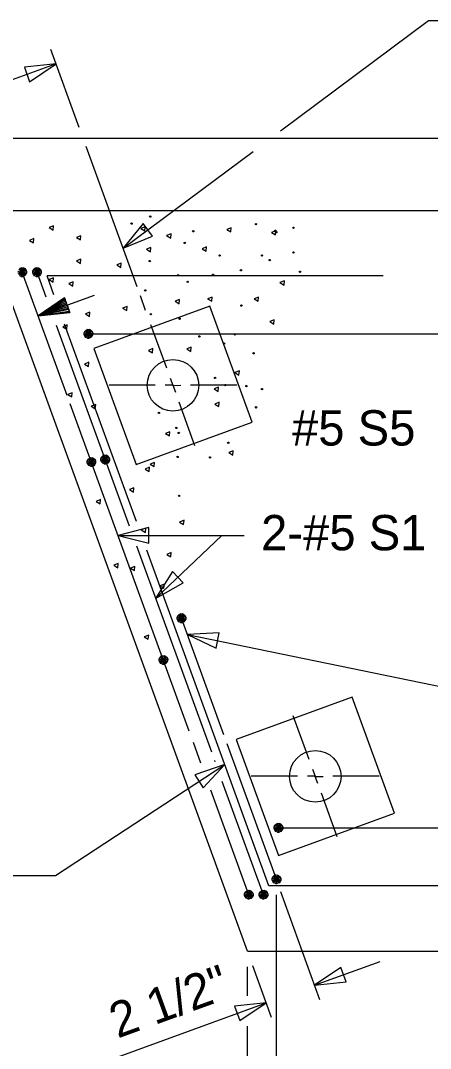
# Model space of a CAD drawing. Extents: x 0 to 177, y -1 to 130.
# Drawn here: x 127.362 to 129.022, y 89.921 to 94.083 of the extents above; entities that cross this region are included whole.
import ezdxf

# ---------------------------------------------------------------- set-up
doc = ezdxf.new("R2010")
doc.units = 0
for name, color, linetype in [('Arrowhead Terminators CELL', 7, 'Continuous'), ('Dimension Lines', 7, 'Continuous'), ('Rebar Lines', 7, 'Continuous'), ('Sup Concrete Girder Lines', 7, 'Continuous'), ('Sup Cored Slab Unit', 7, 'Continuous'), ('Text', 7, 'Continuous')]:
    doc.layers.add(name, color=color, linetype=linetype)

msp = doc.modelspace()

# ---------------------------------------------------------------- linework, layer by layer
at = {"layer": 'Arrowhead Terminators CELL'}
for points in [[(127.5058, 93.9076), (127.3776, 93.8942), (127.399, 93.8354)], [(127.7774, 93.1611), (127.8963, 93.2108), (127.859, 93.2609)], [(127.757, 91.9988), (127.882, 91.9675), (127.8819, 92.03)], [(127.9083, 91.7434), (128.0204, 91.8069), (127.9773, 91.8522)], [(128.0376, 91.5979), (128.1537, 91.5421), (128.1663, 91.6034)], [(128.1893, 91.0712), (128.0676, 91.0288), (128.1019, 90.9765)], [(128.5529, 90.1772), (128.6811, 90.1906), (128.6597, 90.2493)], [(128.3572, 90.1059), (128.2291, 90.0926), (128.2504, 90.0338)]]:
    msp.add_lwpolyline(points, close=True, dxfattribs=at)
at = {"layer": 'Dimension Lines'}
for p, q in [((127.5996, 93.6496), (127.4843, 93.9663)), ((127.5058, 93.9076), (127.0359, 93.7366)), ((130.9813, 93.6051), (127.1894, 93.6051)), ((127.834, 93.0056), (127.6275, 93.573)), ((127.6608, 92.9704), (127.4335, 92.8876)), ((127.8688, 92.9098), (127.8474, 92.9686)), ((127.9545, 92.675), (127.8903, 92.8511)), ((127.9079, 92.6064), (127.7204, 92.6063)), ((128.2385, 92.6063), (128.051, 92.6063)), ((128.0685, 92.3615), (128.0044, 92.5377)), ((127.757, 91.9988), (128.1767, 91.9988)), ((128.5305, 91.0918), (128.4664, 91.268)), ((128.4839, 91.0232), (128.2964, 91.0232)), ((128.8146, 91.0232), (128.627, 91.0232)), ((128.6446, 90.7784), (128.5804, 90.9545)), ((128.3985, 89.6325), (128.3985, 90.5438)), ((128.5743, 90.1184), (128.4156, 90.5548)), ((128.5529, 90.1772), (128.8183, 90.2738)), ((128.2813, 90.1345), (128.2813, 90.2521)), ((128.3786, 90.0472), (128.3027, 90.2559)), ((127.7272, 89.8766), (128.3572, 90.1059)), ((128.2813, 88.9658), (128.2813, 90.0109))]:
    msp.add_line(p, q, dxfattribs=at)
for points in [[(128.4152, 93.6366), (129.0144, 94.0831), (129.5734, 94.0831)], [(127.7774, 93.1611), (128.3039, 93.5535)], [(127.5509, 92.9304), (127.5531, 92.9246), (127.4335, 92.8876), (127.5553, 92.9187), (127.5574, 92.9128), (127.4335, 92.8876), (127.5595, 92.9069), (127.5616, 92.9011), (127.4335, 92.8876), (127.5402, 92.9598), (127.5424, 92.9538), (127.4335, 92.8876), (127.5445, 92.948), (127.5467, 92.9421), (127.4335, 92.8876), (127.5489, 92.9363), (127.5616, 92.9011), (127.5402, 92.9598), (127.4335, 92.8876), (127.5616, 92.9011)], [(127.9686, 92.6357), (127.9794, 92.6063), (127.9479, 92.6062)], [(127.9904, 92.5766), (127.9797, 92.6061), (128.0111, 92.6062)], [(127.9083, 91.7434), (128.1767, 91.9988), (128.2676, 91.9988)], [(128.0376, 91.5979), (132.1073, 90.7605), (132.2093, 90.7605)], [(127.2472, 90.6214), (127.5032, 90.6214), (128.1893, 91.0712)], [(128.5446, 91.0526), (128.5555, 91.0232), (128.5239, 91.0231)], [(128.5665, 90.9935), (128.5558, 91.023), (128.5872, 91.023)]]:
    msp.add_lwpolyline(points, dxfattribs=at)
at = {"layer": 'Rebar Lines'}
for p, q in [((127.5509, 92.5651), (127.3691, 93.0646)), ((127.4655, 92.9637), (127.4288, 93.0646)), ((128.8304, 93.049), (127.4694, 93.049)), ((127.4973, 92.9723), (127.4694, 93.049)), ((127.8315, 92.0542), (127.5406, 92.8534)), ((127.8032, 92.0362), (127.5075, 92.8486)), ((127.637, 92.8146), (130.3245, 92.8146)), ((127.7428, 92.0378), (127.5632, 92.5312)), ((128.0456, 91.2056), (127.7427, 92.0378)), ((128.1363, 91.1208), (127.8328, 91.9548)), ((128.368, 90.5803), (127.8736, 91.9385)), ((128.1858, 91.1908), (128.0137, 91.6634)), ((128.0925, 91.0769), (128.0623, 91.1599)), ((128.3985, 90.6063), (128.1987, 91.1551)), ((128.1506, 91.0814), (128.1486, 91.0869)), ((128.3463, 90.5438), (128.1793, 91.0026)), ((128.2865, 90.5438), (128.1326, 90.9667)), ((128.4065, 90.8146), (131.094, 90.8146)), ((129.729, 90.5803), (128.368, 90.5803))]:
    msp.add_line(p, q, dxfattribs=at)
for points in [[(127.3517, 93.0616), (127.3691, 93.0646), (127.3864, 93.0677), (127.3839, 93.0742), (127.3691, 93.0646), (127.3792, 93.0791), (127.3729, 93.0819), (127.3691, 93.0646), (127.366, 93.082), (127.3596, 93.0795), (127.3691, 93.0646), (127.3546, 93.0747)], [(127.3518, 93.0684), (127.3691, 93.0646), (127.3542, 93.0552)], [(127.3596, 93.0795), (127.366, 93.082), (127.3729, 93.0819), (127.3792, 93.0791), (127.3839, 93.0742), (127.3864, 93.0677), (127.3863, 93.0609), (127.3835, 93.0546), (127.3786, 93.0498), (127.3722, 93.0473), (127.3652, 93.0475), (127.359, 93.0502)], [(127.359, 93.0502), (127.3691, 93.0646), (127.3652, 93.0475), (127.3722, 93.0473), (127.3691, 93.0646), (127.3786, 93.0498), (127.3835, 93.0546), (127.3691, 93.0646), (127.3863, 93.0609)], [(127.4115, 93.0616), (127.4116, 93.0684), (127.4143, 93.0747), (127.4193, 93.0795), (127.4258, 93.082), (127.4326, 93.0818), (127.4389, 93.0791), (127.4437, 93.0741), (127.4462, 93.0677), (127.446, 93.0608), (127.4433, 93.0545), (127.4384, 93.0497), (127.4319, 93.0472), (127.425, 93.0474), (127.4188, 93.0502), (127.414, 93.0551), (127.4115, 93.0616), (127.4288, 93.0646), (127.4462, 93.0677), (127.4437, 93.0741), (127.4288, 93.0646), (127.4389, 93.0791), (127.4326, 93.0818), (127.4288, 93.0646), (127.4258, 93.082), (127.4193, 93.0795), (127.4288, 93.0646), (127.4143, 93.0747), (127.4116, 93.0684), (127.4288, 93.0646), (127.414, 93.0551), (127.4188, 93.0502), (127.4288, 93.0646), (127.425, 93.0474), (127.4319, 93.0472), (127.4288, 93.0646), (127.4384, 93.0497), (127.4433, 93.0545), (127.4288, 93.0646), (127.446, 93.0608)], [(127.6198, 92.8116), (127.6199, 92.8184), (127.6226, 92.8247), (127.6276, 92.8295), (127.634, 92.832), (127.6408, 92.8319), (127.6471, 92.8291), (127.6519, 92.8241), (127.6544, 92.8177), (127.6542, 92.8108), (127.6515, 92.8045), (127.6466, 92.7997), (127.6401, 92.7972), (127.6332, 92.7974), (127.627, 92.8002), (127.6222, 92.8052), (127.6198, 92.8116), (127.637, 92.8146), (127.6544, 92.8177), (127.6519, 92.8241), (127.637, 92.8146), (127.6471, 92.8291), (127.6408, 92.8319), (127.637, 92.8146), (127.634, 92.832), (127.6276, 92.8295), (127.637, 92.8146), (127.6226, 92.8247), (127.6199, 92.8184), (127.637, 92.8146), (127.6222, 92.8052), (127.627, 92.8002), (127.637, 92.8146), (127.6332, 92.7974), (127.6401, 92.7972), (127.637, 92.8146), (127.6466, 92.7997), (127.6515, 92.8045), (127.637, 92.8146), (127.6542, 92.8108)], [(127.6316, 92.2926), (127.6317, 92.2994), (127.6345, 92.3057), (127.6395, 92.3105), (127.6459, 92.313), (127.6527, 92.3129), (127.659, 92.3101), (127.6638, 92.3052), (127.6663, 92.2987), (127.6661, 92.2919), (127.6634, 92.2856), (127.6585, 92.2808), (127.652, 92.2783), (127.6451, 92.2784), (127.6389, 92.2812), (127.6341, 92.2862), (127.6316, 92.2926), (127.6489, 92.2956), (127.6663, 92.2987), (127.6638, 92.3052), (127.6489, 92.2956), (127.659, 92.3101), (127.6527, 92.3129), (127.6489, 92.2956), (127.6459, 92.313), (127.6395, 92.3105), (127.6489, 92.2956), (127.6345, 92.3057), (127.6317, 92.2994), (127.6489, 92.2956), (127.6341, 92.2862), (127.6389, 92.2812), (127.6489, 92.2956), (127.6451, 92.2784), (127.652, 92.2783), (127.6489, 92.2956), (127.6585, 92.2808), (127.6634, 92.2856), (127.6489, 92.2956), (127.6661, 92.2919)], [(127.6878, 92.3025), (127.6879, 92.3093), (127.6906, 92.3156), (127.6956, 92.3204), (127.7021, 92.3229), (127.7089, 92.3228), (127.7152, 92.32), (127.7199, 92.3151), (127.7225, 92.3086), (127.7223, 92.3018), (127.7196, 92.2955), (127.7146, 92.2907), (127.7082, 92.2882), (127.7013, 92.2883), (127.695, 92.2911), (127.6902, 92.296), (127.6878, 92.3025), (127.7051, 92.3056), (127.7225, 92.3086), (127.7199, 92.3151), (127.7051, 92.3056), (127.7152, 92.32), (127.7089, 92.3228), (127.7051, 92.3056), (127.7021, 92.3229), (127.6956, 92.3204), (127.7051, 92.3056), (127.6906, 92.3156), (127.6879, 92.3093), (127.7051, 92.3056), (127.6902, 92.296), (127.695, 92.2911), (127.7051, 92.3056), (127.7013, 92.2883), (127.7082, 92.2882), (127.7051, 92.3056), (127.7146, 92.2907), (127.7196, 92.2955), (127.7051, 92.3056), (127.7223, 92.3018)], [(127.9964, 91.6604), (127.9965, 91.6672), (127.9992, 91.6735), (128.0042, 91.6783), (128.0106, 91.6808), (128.0175, 91.6807), (128.0238, 91.6779), (128.0286, 91.673), (128.0311, 91.6665), (128.0309, 91.6597), (128.0281, 91.6534), (128.0232, 91.6486), (128.0168, 91.6461), (128.0099, 91.6463), (128.0036, 91.649), (127.9988, 91.654), (127.9964, 91.6604), (128.0137, 91.6634), (128.0311, 91.6665), (128.0286, 91.673), (128.0137, 91.6634), (128.0238, 91.6779), (128.0175, 91.6807), (128.0137, 91.6634), (128.0106, 91.6808), (128.0042, 91.6783), (128.0137, 91.6634), (127.9992, 91.6735), (127.9965, 91.6672), (128.0137, 91.6634), (127.9988, 91.654), (128.0036, 91.649), (128.0137, 91.6634), (128.0099, 91.6463), (128.0168, 91.6461), (128.0137, 91.6634), (128.0232, 91.6486), (128.0281, 91.6534), (128.0137, 91.6634), (128.0309, 91.6597)], [(127.9233, 91.491), (127.9234, 91.4979), (127.9262, 91.5042), (127.9312, 91.509), (127.9376, 91.5114), (127.9445, 91.5113), (127.9508, 91.5085), (127.9555, 91.5035), (127.958, 91.4971), (127.9578, 91.4903), (127.9551, 91.484), (127.9501, 91.4792), (127.9437, 91.4767), (127.9368, 91.4768), (127.9305, 91.4796), (127.9258, 91.4846), (127.9233, 91.491), (127.9406, 91.4941), (127.958, 91.4971), (127.9555, 91.5035), (127.9406, 91.4941), (127.9508, 91.5085), (127.9445, 91.5113), (127.9406, 91.4941), (127.9376, 91.5114), (127.9312, 91.509), (127.9406, 91.4941), (127.9262, 91.5042), (127.9234, 91.4979), (127.9406, 91.4941), (127.9258, 91.4846), (127.9305, 91.4796), (127.9406, 91.4941), (127.9368, 91.4768), (127.9437, 91.4767), (127.9406, 91.4941), (127.9501, 91.4792), (127.9551, 91.484), (127.9406, 91.4941), (127.9578, 91.4903)], [(128.3892, 90.8116), (128.3893, 90.8184), (128.3921, 90.8247), (128.397, 90.8295), (128.4035, 90.832), (128.4103, 90.8319), (128.4166, 90.8291), (128.4213, 90.8241), (128.4238, 90.8177), (128.4237, 90.8108), (128.4209, 90.8045), (128.416, 90.7997), (128.4096, 90.7972), (128.4027, 90.7974), (128.3964, 90.8002), (128.3916, 90.8052), (128.3892, 90.8116), (128.4065, 90.8146), (128.4238, 90.8177), (128.4213, 90.8241), (128.4065, 90.8146), (128.4166, 90.8291), (128.4103, 90.8319), (128.4065, 90.8146), (128.4035, 90.832), (128.397, 90.8295), (128.4065, 90.8146), (128.3921, 90.8247), (128.3893, 90.8184), (128.4065, 90.8146), (128.3916, 90.8052), (128.3964, 90.8002), (128.4065, 90.8146), (128.4027, 90.7974), (128.4096, 90.7972), (128.4065, 90.8146), (128.416, 90.7997), (128.4209, 90.8045), (128.4065, 90.8146), (128.4237, 90.8108)], [(128.3812, 90.6032), (128.3813, 90.6101), (128.384, 90.6164), (128.389, 90.6212), (128.3954, 90.6236), (128.4023, 90.6235), (128.4086, 90.6207), (128.4133, 90.6157), (128.4159, 90.6093), (128.4156, 90.6025), (128.4129, 90.5962), (128.408, 90.5914), (128.4016, 90.5889), (128.3947, 90.589), (128.3884, 90.5918), (128.3836, 90.5968), (128.3812, 90.6032), (128.3985, 90.6063), (128.4159, 90.6093), (128.4133, 90.6157), (128.3985, 90.6063), (128.4086, 90.6207), (128.4023, 90.6235), (128.3985, 90.6063), (128.3954, 90.6236), (128.389, 90.6212), (128.3985, 90.6063), (128.384, 90.6164), (128.3813, 90.6101), (128.3985, 90.6063), (128.3836, 90.5968), (128.3884, 90.5918), (128.3985, 90.6063), (128.3947, 90.589), (128.4016, 90.5889), (128.3985, 90.6063), (128.408, 90.5914), (128.4129, 90.5962), (128.3985, 90.6063), (128.4156, 90.6025)], [(128.2692, 90.5407), (128.2693, 90.5476), (128.2721, 90.5539), (128.277, 90.5587), (128.2835, 90.5611), (128.2903, 90.561), (128.2966, 90.5582), (128.3013, 90.5532), (128.3038, 90.5468), (128.3037, 90.54), (128.3009, 90.5337), (128.296, 90.5289), (128.2896, 90.5264), (128.2827, 90.5265), (128.2764, 90.5293), (128.2716, 90.5343), (128.2692, 90.5407), (128.2865, 90.5438), (128.3038, 90.5468), (128.3013, 90.5532), (128.2865, 90.5438), (128.2966, 90.5582), (128.2903, 90.561), (128.2865, 90.5438), (128.2835, 90.5611), (128.277, 90.5587), (128.2865, 90.5438), (128.2721, 90.5539), (128.2693, 90.5476), (128.2865, 90.5438), (128.2716, 90.5343), (128.2764, 90.5293), (128.2865, 90.5438), (128.2827, 90.5265), (128.2896, 90.5264), (128.2865, 90.5438), (128.296, 90.5289), (128.3009, 90.5337), (128.2865, 90.5438), (128.3037, 90.54)], [(128.3289, 90.5407), (128.3291, 90.5476), (128.3318, 90.5539), (128.3368, 90.5587), (128.3433, 90.5611), (128.3501, 90.561), (128.3564, 90.5582), (128.3611, 90.5533), (128.3636, 90.5468), (128.3635, 90.54), (128.3607, 90.5337), (128.3558, 90.5289), (128.3493, 90.5264), (128.3425, 90.5266), (128.3362, 90.5293), (128.3314, 90.5343), (128.3289, 90.5407), (128.3463, 90.5438), (128.3636, 90.5468), (128.3611, 90.5533), (128.3463, 90.5438), (128.3564, 90.5582), (128.3501, 90.561), (128.3463, 90.5438), (128.3433, 90.5611), (128.3368, 90.5587), (128.3463, 90.5438), (128.3318, 90.5539), (128.3291, 90.5476), (128.3463, 90.5438), (128.3314, 90.5343), (128.3362, 90.5293), (128.3463, 90.5438), (128.3425, 90.5266), (128.3493, 90.5264), (128.3463, 90.5438), (128.3558, 90.5289), (128.3607, 90.5337), (128.3463, 90.5438), (128.3635, 90.54)]]:
    msp.add_lwpolyline(points, dxfattribs=at)
at = {"layer": 'Sup Concrete Girder Lines'}
for p, q in [((127.2519, 93.3146), (132.0247, 93.3146)), ((128.2813, 90.3146), (127.2108, 93.2559)), ((128.2813, 90.3146), (132.0247, 90.3146))]:
    msp.add_line(p, q, dxfattribs=at)
for points in [[(127.4942, 93.2346), (127.4956, 93.2518), (127.4777, 93.2447), (127.4942, 93.2346)], [(127.8657, 93.2314), (127.8672, 93.2486), (127.8492, 93.2415), (127.8657, 93.2314)], [(128.214, 93.2273), (128.2155, 93.2445), (128.1975, 93.2374), (128.214, 93.2273)], [(128.3943, 93.215), (128.3958, 93.2322), (128.3778, 93.2251), (128.3943, 93.215)], [(127.4147, 93.183), (127.4162, 93.2002), (127.3982, 93.1931), (127.4147, 93.183)], [(127.6054, 93.1948), (127.6069, 93.2121), (127.5889, 93.205), (127.6054, 93.1948)], [(127.9702, 93.2027), (127.9716, 93.2199), (127.9537, 93.2128), (127.9702, 93.2027)], [(127.8883, 93.1473), (127.8897, 93.1646), (127.8717, 93.1575), (127.8883, 93.1473)], [(128.1136, 93.1494), (128.1151, 93.1667), (128.0971, 93.1595), (128.1136, 93.1494)], [(127.6054, 93.0995), (127.6069, 93.1168), (127.5889, 93.1096), (127.6054, 93.0995)], [(127.7684, 93.0836), (127.7698, 93.1008), (127.7518, 93.0937), (127.7684, 93.0836)], [(127.4942, 93.024), (127.4956, 93.0413), (127.4777, 93.0341), (127.4942, 93.024)], [(127.5737, 93.0081), (127.5751, 93.0254), (127.5572, 93.0182), (127.5737, 93.0081)], [(128.4291, 93.0121), (128.4306, 93.0294), (128.4126, 93.0222), (128.4291, 93.0121)], [(128.005, 92.9363), (128.0065, 92.9535), (127.9885, 92.9464), (128.005, 92.9363)], [(128.1362, 92.9466), (128.1376, 92.9638), (128.1197, 92.9567), (128.1362, 92.9466)], [(128.3247, 92.9466), (128.3261, 92.9638), (128.3081, 92.9567), (128.3247, 92.9466)], [(127.6412, 92.885), (127.6427, 92.9022), (127.6247, 92.8951), (127.6412, 92.885)], [(127.7922, 92.9088), (127.7936, 92.926), (127.7756, 92.9189), (127.7922, 92.9088)], [(128.3882, 92.8544), (128.3897, 92.8716), (128.3717, 92.8645), (128.3882, 92.8544)], [(127.5498, 92.8333), (127.5513, 92.8506), (127.5333, 92.8434), (127.5498, 92.8333)], [(127.8964, 92.7376), (127.8979, 92.7548), (127.8799, 92.7477), (127.8964, 92.7376)], [(128.0522, 92.7437), (128.0536, 92.7609), (128.0356, 92.7538), (128.0522, 92.7437)], [(127.6372, 92.6823), (127.6387, 92.6996), (127.6207, 92.6925), (127.6372, 92.6823)], [(128.2468, 92.6474), (128.2483, 92.6646), (128.2303, 92.6575), (128.2468, 92.6474)], [(127.5697, 92.5592), (127.5711, 92.5764), (127.5531, 92.5693), (127.5697, 92.5592)], [(128.1628, 92.5818), (128.1642, 92.5991), (128.1463, 92.5919), (128.1628, 92.5818)], [(127.665, 92.5115), (127.6665, 92.5288), (127.6485, 92.5216), (127.665, 92.5115)], [(128.1649, 92.5204), (128.1663, 92.5376), (128.1484, 92.5305), (128.1649, 92.5204)], [(127.9653, 92.4011), (127.9668, 92.4183), (127.9488, 92.4112), (127.9653, 92.4011)], [(128.2222, 92.3237), (128.2237, 92.3409), (128.2057, 92.3338), (128.2222, 92.3237)], [(127.8836, 92.2572), (127.885, 92.2744), (127.8671, 92.2673), (127.8836, 92.2572)], [(127.9034, 92.2771), (127.9049, 92.2943), (127.8869, 92.2872), (127.9034, 92.2771)], [(127.82, 92.1738), (127.8214, 92.191), (127.8035, 92.1839), (127.82, 92.1738)], [(127.6849, 92.1261), (127.6864, 92.1433), (127.6684, 92.1362), (127.6849, 92.1261)], [(127.8677, 92.0109), (127.8691, 92.0281), (127.8512, 92.021), (127.8677, 92.0109)], [(128.0226, 92.0427), (128.0241, 92.0599), (128.0061, 92.0528), (128.0226, 92.0427)], [(127.971, 91.9116), (127.9724, 91.9288), (127.9545, 91.9217), (127.971, 91.9116)], [(127.7564, 91.8679), (127.7579, 91.8851), (127.7399, 91.878), (127.7564, 91.8679)], [(127.824, 91.8559), (127.8254, 91.8732), (127.8075, 91.866), (127.824, 91.8559)], [(127.9431, 91.7844), (127.9446, 91.8017), (127.9266, 91.7945), (127.9431, 91.7844)], [(127.8796, 91.5778), (127.8811, 91.5951), (127.8631, 91.5879), (127.8796, 91.5778)]]:
    msp.add_lwpolyline(points, dxfattribs=at)
for centre, radius in [((127.8877, 93.2895), 0.00273), ((127.8119, 93.2609), 0.00273), ((128.0618, 93.2301), 0.00273), ((128.3159, 93.2588), 0.00273), ((128.3938, 93.2322), 0.00273), ((128.3979, 93.226), 0.00273), ((128.4676, 93.2445), 0.00273), ((128.027, 93.183), 0.00273), ((128.4676, 93.1441), 0.00273), ((127.8856, 93.1092), 0.00273), ((128.1684, 93.1318), 0.00273), ((128.3405, 93.1318), 0.00273), ((128.3713, 93.1133), 0.00273), ((128.2545, 93.0723), 0.00273), ((128.4942, 93.0662), 0.00273), ((128.0004, 93.0519), 0.00273), ((128.0393, 93.0253), 0.00273), ((128.1417, 93.0539), 0.00273), ((127.8672, 92.9904), 0.00273), ((127.8898, 92.8941), 0.00273), ((128.2565, 92.929), 0.00273), ((128.0065, 92.8757), 0.00273), ((128.2299, 92.8121), 0.00273), ((128.0864, 92.804), 0.00273), ((128.1868, 92.7753), 0.00273), ((128.3057, 92.7363), 0.00273), ((127.9794, 92.6063), 0.1042), ((128.15, 92.6359), 0.00273), ((128.191, 92.6072), 0.00273), ((128.277, 92.6031), 0.00273), ((128.3405, 92.5908), 0.00273), ((128.3159, 92.5171), 0.00273), ((127.9225, 92.4945), 0.00273), ((127.9926, 92.4338), 0.00273), ((128.0029, 92.4133), 0.00273), ((128.2033, 92.3736), 0.00273), ((127.9984, 92.3163), 0.00273), ((128.1295, 92.3143), 0.00273), ((128.0045, 92.1585), 0.00273), ((128.5558, 91.023), 0.1042)]:
    msp.add_circle(centre, radius, dxfattribs=at)
at = {"layer": 'Sup Cored Slab Unit'}
for points in [[(128.1288, 92.9267), (127.659, 92.7557), (127.83, 92.2859), (128.2999, 92.4569)], [(128.7052, 91.3434), (128.2354, 91.1724), (128.4064, 90.7025), (128.8762, 90.8736)]]:
    msp.add_lwpolyline(points, close=True, dxfattribs=at)

# ---------------------------------------------------------------- texts
at = {"layer": 'Text'}
for s, p in [('#5 S5', (128.4614, 92.3624)), ('2-#5 S1', (128.3362, 91.9382))]:
    msp.add_text(s, height=0.14302, dxfattribs=at).set_placement(p)
msp.add_text('2 1/2"', height=0.14302, rotation=19.9967, dxfattribs=at).set_placement((127.755, 89.9609))

doc.saveas('drawing.dxf')
